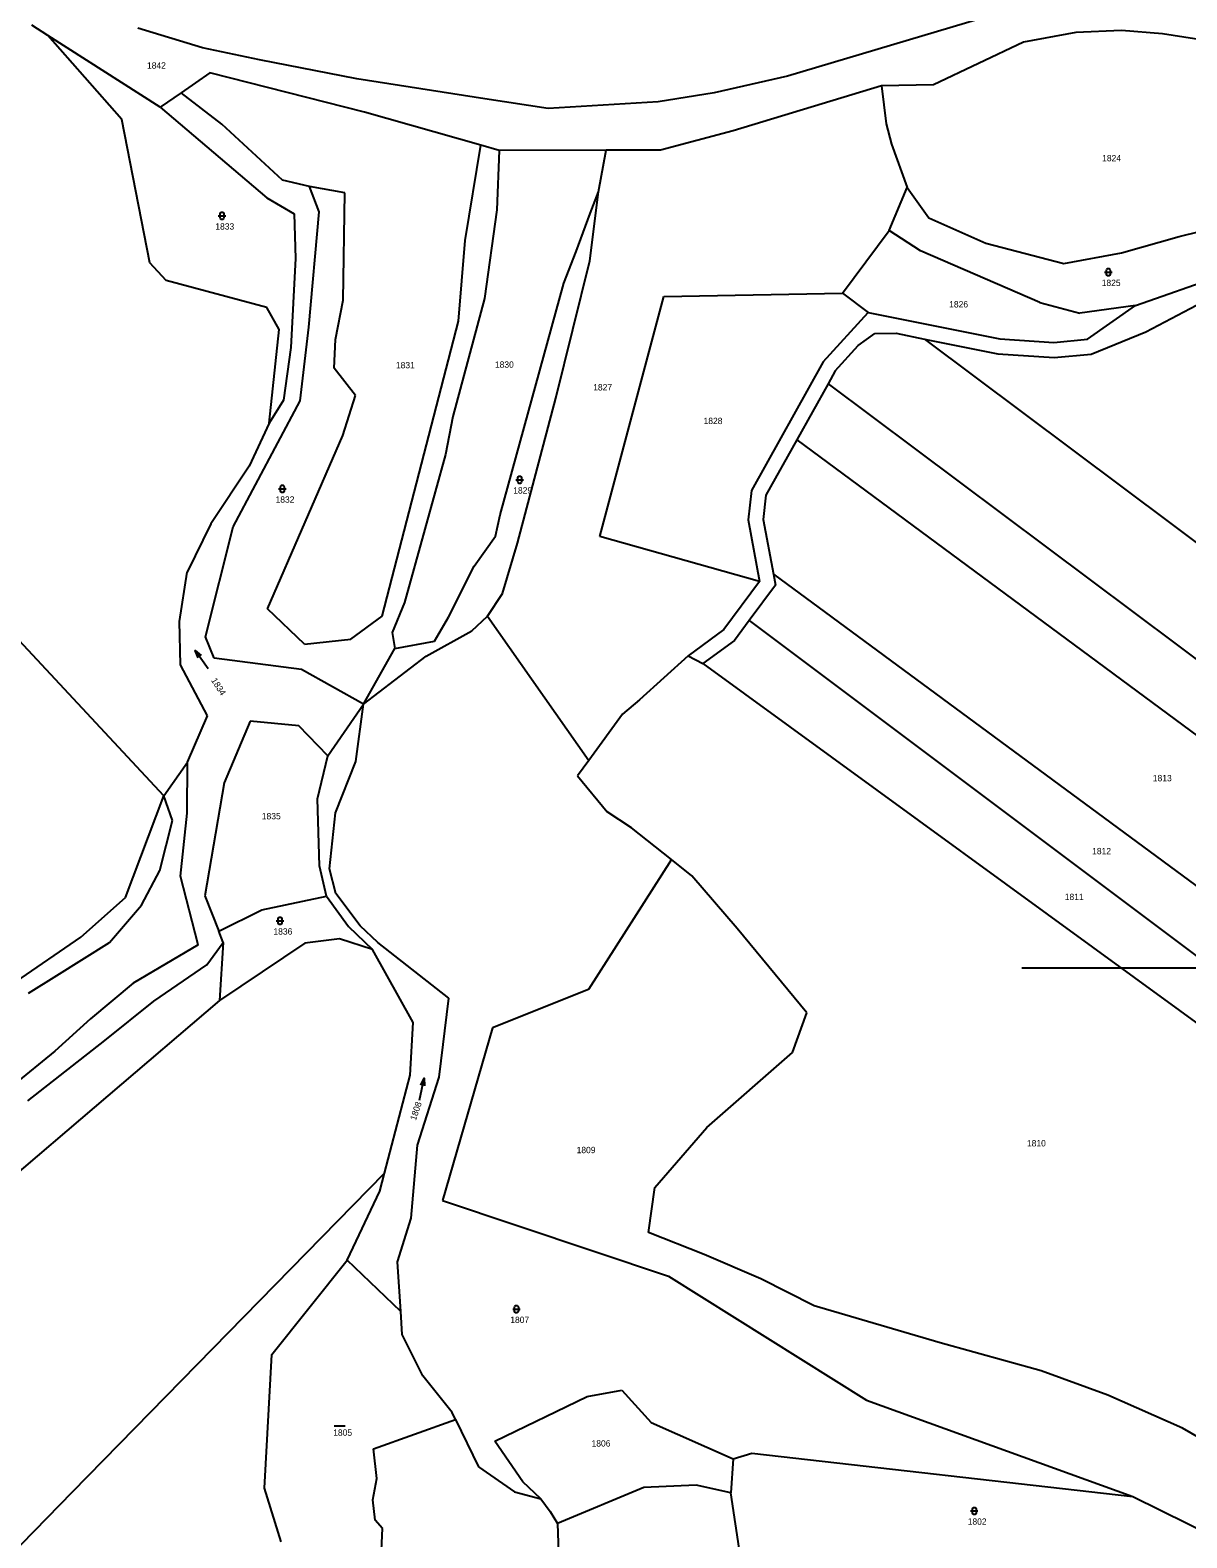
# Model space of a CAD drawing. Extents: x -802857 to -799647, y -1020285 to -1015884.
# Drawn here: x -802140.5 to -801830.8, y -1017652.7 to -1017248.9 of the extents above; entities that cross this region are included whole.
import ezdxf

# ---------------------------------------------------------------- set-up
doc = ezdxf.new("R2010")
doc.units = 0
for name, color, linetype in [('Default', 7, 'Continuous'), ('KLADY_ZMVM', 7, 'Continuous'), ('KN_HRANICE', 7, 'Continuous'), ('KN_KULTURY', 7, 'Continuous'), ('KN_PARCELY', 7, 'Continuous')]:
    doc.layers.add(name, color=color, linetype=linetype)

# ---------------------------------------------------------------- blocks, each defined once
blk = doc.blocks.new('316')
at = {"layer": 'Default'}
for points in [[(-1, 1), (0.27, 1), (1, 1)], [(-0.5, 1.5), (-0.4, 1.79), (-0.15, 1.97), (0.16, 1.97), (0.41, 1.79), (0.51, 1.5), (0.51, 0.5), (0.41, 0.21), (0.16, 0.03), (-0.15, 0.03), (-0.4, 0.21), (-0.5, 0.5), (-0.5, 1.5)]]:
    blk.add_lwpolyline(points, dxfattribs=at)
blk = doc.blocks.new('802')
at = {"layer": 'Default'}
blk.add_line((-3, 0), (3, 0), dxfattribs=at)
blk.add_lwpolyline([(1, 0.5), (3, 0), (1, -0.5)], dxfattribs=at)
blk = doc.blocks.new('804')
at = {"layer": 'Default'}
blk.add_line((-1.5, 0), (1.5, 0), dxfattribs=at)

msp = doc.modelspace()

# ---------------------------------------------------------------- linework, layer by layer
at = {"layer": 'KLADY_ZMVM'}
msp.add_lwpolyline([(-801875, -1017500), (-801250, -1017500), (-801043.11, -1017500)], dxfattribs=at)
at = {"layer": 'KN_HRANICE'}
for p, q in [((-802135.82, -1017250.34), (-802140.07, -1017247.63)), ((-802094.38, -1017253.69), (-802111.69, -1017248.4)), ((-801885.86, -1017245.79), (-801937.77, -1017261.22)), ((-802115.97, -1017272.85), (-802135.82, -1017250.34)), ((-802105.66, -1017269.56), (-802135.82, -1017250.34)), ((-801874.58, -1017252.18), (-801898.61, -1017263.57)), ((-801860.52, -1017249.56), (-801874.58, -1017252.18)), ((-801848.33, -1017249.03), (-801860.52, -1017249.56)), ((-801837.36, -1017249.87), (-801848.33, -1017249.03)), ((-801825.91, -1017251.69), (-801837.36, -1017249.87)), ((-802079.15, -1017256.83), (-802094.38, -1017253.69)), ((-802092.36, -1017260.39), (-802100.06, -1017265.7)), ((-802050.96, -1017270.85), (-802092.36, -1017260.39)), ((-802053.05, -1017261.93), (-802079.15, -1017256.83)), ((-802018.77, -1017267.32), (-802053.05, -1017261.93)), ((-801937.77, -1017261.22), (-801957.35, -1017265.73)), ((-801912.59, -1017263.88), (-801952.27, -1017275.87)), ((-801898.61, -1017263.57), (-801912.59, -1017263.88)), ((-801912.59, -1017263.88), (-801911.34, -1017274.02)), ((-802100.06, -1017265.7), (-802105.66, -1017269.56)), ((-802089.22, -1017274.06), (-802100.06, -1017265.7)), ((-802001.86, -1017269.94), (-802018.77, -1017267.32)), ((-801972.34, -1017268.15), (-802001.86, -1017269.94)), ((-801957.35, -1017265.73), (-801972.34, -1017268.15)), ((-802105.66, -1017269.56), (-802077.17, -1017293.84)), ((-802019.81, -1017279.73), (-802050.96, -1017270.85)), ((-802108.43, -1017311.28), (-802115.97, -1017272.85)), ((-802072.93, -1017289.09), (-802089.22, -1017274.06)), ((-801952.27, -1017275.87), (-801971.78, -1017281.07)), ((-801911.34, -1017274.02), (-801909.91, -1017279.49)), ((-802024.05, -1017305.27), (-802019.81, -1017279.73)), ((-802014.98, -1017281.11), (-802019.81, -1017279.73)), ((-801909.91, -1017279.49), (-801905.73, -1017291.03)), ((-802014.98, -1017281.11), (-802015.53, -1017297.03)), ((-801986.28, -1017281.08), (-802014.98, -1017281.11)), ((-801988.37, -1017292.2), (-801986.28, -1017281.08)), ((-801971.78, -1017281.07), (-801986.28, -1017281.08)), ((-802065.76, -1017290.83), (-802072.93, -1017289.09)), ((-802063.17, -1017297.59), (-802065.76, -1017290.83)), ((-802056.25, -1017292.52), (-802065.76, -1017290.83)), ((-802056.66, -1017321.24), (-802056.25, -1017292.52)), ((-801990.7, -1017310.73), (-801988.37, -1017292.2)), ((-801990.6, -1017297.99), (-801988.37, -1017292.2)), ((-801910.52, -1017302.62), (-801905.73, -1017291.03)), ((-801905.73, -1017291.03), (-801899.92, -1017299.2)), ((-802077.17, -1017293.84), (-802069.8, -1017298.14)), ((-802015.53, -1017297.03), (-802018.85, -1017320.82)), ((-802069.8, -1017298.14), (-802069.48, -1017310.1)), ((-802065.91, -1017328.48), (-802063.17, -1017297.59)), ((-801994.28, -1017308.23), (-801990.6, -1017297.99)), ((-801899.92, -1017299.2), (-801884.62, -1017305.93)), ((-801832.86, -1017304.19), (-801816.89, -1017300.2)), ((-801922.99, -1017319.4), (-801910.52, -1017302.62)), ((-801902.09, -1017308), (-801910.52, -1017302.62)), ((-801848.32, -1017308.55), (-801832.86, -1017304.19)), ((-802025.84, -1017326.85), (-802024.05, -1017305.27)), ((-801997.65, -1017316.67), (-801994.28, -1017308.23)), ((-801870.21, -1017321.88), (-801902.09, -1017308)), ((-801884.62, -1017305.93), (-801863.71, -1017311.42)), ((-801863.71, -1017311.42), (-801848.32, -1017308.55)), ((-802104.1, -1017315.93), (-802108.43, -1017311.28)), ((-802069.48, -1017310.1), (-802070.75, -1017333.91)), ((-801999.74, -1017347.44), (-801990.7, -1017310.73)), ((-802104.72, -1017453.99), (-802234.28, -1017315.12)), ((-802077.12, -1017323.21), (-802104.1, -1017315.93)), ((-802014.71, -1017378.73), (-801997.65, -1017316.67)), ((-801844.56, -1017322.69), (-801821.66, -1017314.59)), ((-802058.72, -1017331.81), (-802056.66, -1017321.24)), ((-802018.85, -1017320.82), (-802027.34, -1017352.4)), ((-801987.95, -1017384.56), (-801970.88, -1017320.22)), ((-801970.88, -1017320.22), (-801922.99, -1017319.4)), ((-801922.99, -1017319.4), (-801916.15, -1017324.52)), ((-801841.82, -1017329.72), (-801824.8, -1017320.76)), ((-802073.83, -1017329.13), (-802077.12, -1017323.21)), ((-801928.21, -1017337.78), (-801916.15, -1017324.52)), ((-801916.15, -1017324.52), (-801880.89, -1017331.62)), ((-801870.21, -1017321.88), (-801859.44, -1017324.75)), ((-801844.56, -1017322.69), (-801859.44, -1017324.75)), ((-801857.38, -1017331.72), (-801844.56, -1017322.69)), ((-802076.48, -1017354.13), (-802073.83, -1017329.13)), ((-802068.2, -1017348.18), (-802065.91, -1017328.48)), ((-802046.3, -1017405.83), (-802025.84, -1017326.85)), ((-802059.12, -1017339.45), (-802058.72, -1017331.81)), ((-801924.94, -1017340.13), (-801918.78, -1017333.36)), ((-801918.78, -1017333.36), (-801914.38, -1017330.18)), ((-801914.38, -1017330.18), (-801908.67, -1017330.11)), ((-801908.67, -1017330.11), (-801901.1, -1017331.64)), ((-801901.1, -1017331.64), (-801881.43, -1017335.59)), ((-801901.1, -1017331.64), (-801752.52, -1017442.84)), ((-801880.89, -1017331.62), (-801866.4, -1017332.56)), ((-801866.4, -1017332.56), (-801857.38, -1017331.72)), ((-801856.42, -1017335.65), (-801841.82, -1017329.72)), ((-802070.75, -1017333.91), (-802072.65, -1017348.05)), ((-801881.43, -1017335.59), (-801866.34, -1017336.57)), ((-801866.34, -1017336.57), (-801856.42, -1017335.65)), ((-802053.38, -1017346.72), (-802059.12, -1017339.45)), ((-801928.21, -1017337.78), (-801947.39, -1017372.21)), ((-801924.94, -1017340.13), (-801926.87, -1017343.6)), ((-801926.87, -1017343.6), (-801935.26, -1017358.65)), ((-801926.87, -1017343.6), (-801768.75, -1017461.94)), ((-802086.2, -1017381.95), (-802068.2, -1017348.18)), ((-802072.65, -1017348.05), (-802076.48, -1017354.13)), ((-802056.78, -1017357.44), (-802053.38, -1017346.72)), ((-802010.06, -1017386.33), (-801999.74, -1017347.44)), ((-802027.34, -1017352.4), (-802029.33, -1017362.55)), ((-802076.48, -1017354.13), (-802081.89, -1017365.72)), ((-802076.93, -1017403.91), (-802056.78, -1017357.44)), ((-801935.26, -1017358.65), (-801943.51, -1017373.46)), ((-801935.26, -1017358.65), (-801779.08, -1017474.09)), ((-802029.33, -1017362.55), (-802034.83, -1017382.57)), ((-802081.89, -1017365.72), (-802092.18, -1017381.13)), ((-801947.39, -1017372.21), (-801948.3, -1017380.1)), ((-801943.51, -1017373.46), (-801944.26, -1017379.96)), ((-802092.18, -1017381.13), (-802098.46, -1017394.03)), ((-802015.89, -1017384.46), (-802014.71, -1017378.73)), ((-801948.3, -1017380.1), (-801945.23, -1017396.56)), ((-801944.26, -1017379.96), (-801941.53, -1017394.58)), ((-802093.54, -1017411.38), (-802086.2, -1017381.95)), ((-802034.83, -1017382.57), (-802040.31, -1017402.18)), ((-802021.65, -1017392.45), (-802015.89, -1017384.46)), ((-801945.23, -1017396.56), (-801987.95, -1017384.56)), ((-802014.08, -1017399.77), (-802010.06, -1017386.33)), ((-802028.5, -1017406.11), (-802021.65, -1017392.45)), ((-802100.54, -1017407.26), (-802098.46, -1017394.03)), ((-801945.23, -1017396.56), (-801954.81, -1017409.47)), ((-801940.98, -1017397.54), (-801947.99, -1017406.99)), ((-801941.53, -1017394.58), (-801940.98, -1017397.54)), ((-801941.53, -1017394.58), (-801799.52, -1017499.3)), ((-802018.05, -1017405.89), (-802014.08, -1017399.77)), ((-802067.06, -1017413.33), (-802076.93, -1017403.91)), ((-802054.67, -1017411.98), (-802046.3, -1017405.83)), ((-802040.31, -1017402.18), (-802043.62, -1017410.23)), ((-802022.25, -1017409.81), (-802018.05, -1017405.89)), ((-802018.05, -1017405.89), (-801990.91, -1017444.47)), ((-802100.23, -1017418.86), (-802100.54, -1017407.26)), ((-802034.52, -1017416.58), (-802022.25, -1017409.81)), ((-802032.22, -1017412.54), (-802028.5, -1017406.11)), ((-801954.81, -1017409.47), (-801964.29, -1017416.44)), ((-801947.99, -1017406.99), (-801951.96, -1017412.34)), ((-801947.99, -1017406.99), (-801809.18, -1017511.2)), ((-802091.22, -1017417.12), (-802093.54, -1017411.38)), ((-802067.06, -1017413.33), (-802054.67, -1017411.98)), ((-802043.62, -1017410.23), (-802042.85, -1017414.5)), ((-802042.85, -1017414.5), (-802032.22, -1017412.54)), ((-801951.96, -1017412.34), (-801960.43, -1017418.57)), ((-802067.89, -1017420.13), (-802091.22, -1017417.12)), ((-802051.27, -1017429.42), (-802042.85, -1017414.5)), ((-802051.27, -1017429.42), (-802034.52, -1017416.58)), ((-801964.29, -1017416.44), (-801977.33, -1017428.3)), ((-801964.29, -1017416.44), (-801960.43, -1017418.57)), ((-802093.06, -1017432.53), (-802100.23, -1017418.86)), ((-802051.27, -1017429.42), (-802067.89, -1017420.13)), ((-801960.43, -1017418.57), (-801819.24, -1017521.36)), ((-802060.85, -1017443.3), (-802051.27, -1017429.42)), ((-802053.3, -1017444.75), (-802051.27, -1017429.42)), ((-801977.33, -1017428.3), (-801981.94, -1017432.13)), ((-802098.34, -1017444.92), (-802093.06, -1017432.53)), ((-802081.64, -1017433.99), (-802088.57, -1017450.52)), ((-802068.53, -1017435.23), (-802081.64, -1017433.99)), ((-801981.94, -1017432.13), (-801990.91, -1017444.47)), ((-802060.85, -1017443.3), (-802068.53, -1017435.23)), ((-802104.72, -1017453.99), (-802098.34, -1017444.92)), ((-802098.44, -1017458.57), (-802098.34, -1017444.92)), ((-802063.57, -1017454.79), (-802060.85, -1017443.3)), ((-802058.8, -1017458.48), (-802053.3, -1017444.75)), ((-801990.91, -1017444.47), (-801993.92, -1017448.6)), ((-801993.92, -1017448.6), (-801986, -1017458.26)), ((-802115.01, -1017481.22), (-802104.72, -1017453.99)), ((-802102.44, -1017460.62), (-802104.72, -1017453.99)), ((-802088.57, -1017450.52), (-802093.7, -1017480.76)), ((-802063.08, -1017472.7), (-802063.57, -1017454.79)), ((-802060.32, -1017473.5), (-802058.8, -1017458.48)), ((-801979.48, -1017462.54), (-801986, -1017458.26)), ((-802105.82, -1017473.99), (-802102.44, -1017460.62)), ((-802100.3, -1017475.48), (-802098.44, -1017458.57)), ((-801968.81, -1017471.06), (-801979.48, -1017462.54)), ((-802110.74, -1017483.29), (-802105.82, -1017473.99)), ((-802061.2, -1017480.82), (-802063.08, -1017472.7)), ((-802058.68, -1017480.13), (-802060.32, -1017473.5)), ((-801968.81, -1017471.06), (-801991.01, -1017505.82)), ((-801963.34, -1017475.43), (-801968.81, -1017471.06)), ((-802095.56, -1017493.88), (-802100.3, -1017475.48)), ((-801951.18, -1017489.47), (-801963.34, -1017475.43)), ((-802126.91, -1017491.79), (-802115.01, -1017481.22)), ((-802093.7, -1017480.76), (-802089.98, -1017490.25)), ((-802078.47, -1017484.51), (-802061.2, -1017480.82)), ((-802061.2, -1017480.82), (-802055.25, -1017488.94)), ((-802052.12, -1017488.76), (-802058.68, -1017480.13)), ((-802119.31, -1017493.23), (-802110.74, -1017483.29)), ((-802089.98, -1017490.25), (-802078.47, -1017484.51)), ((-802088.79, -1017493.29), (-802089.98, -1017490.25)), ((-802055.25, -1017488.94), (-802048.87, -1017495.15)), ((-802047.43, -1017493.24), (-802052.12, -1017488.76)), ((-801932.6, -1017512.07), (-801951.18, -1017489.47)), ((-802144.39, -1017503.8), (-802126.91, -1017491.79)), ((-802133.41, -1017502.05), (-802119.31, -1017493.23)), ((-802095.56, -1017493.88), (-802112.95, -1017504.15)), ((-802093.25, -1017499.27), (-802088.79, -1017493.29)), ((-802088.79, -1017493.29), (-802089.8, -1017508.76)), ((-802066.93, -1017493.44), (-802089.8, -1017508.76)), ((-802057.71, -1017492.3), (-802066.93, -1017493.44)), ((-802048.87, -1017495.15), (-802057.71, -1017492.3)), ((-802028.39, -1017508.13), (-802047.43, -1017493.24)), ((-802037.98, -1017514.66), (-802048.87, -1017495.15)), ((-802140.95, -1017506.78), (-802133.41, -1017502.05)), ((-802107.41, -1017508.95), (-802093.25, -1017499.27)), ((-802112.95, -1017504.15), (-802124.38, -1017513.72)), ((-801991.01, -1017505.82), (-802016.71, -1017516.13)), ((-802089.8, -1017508.76), (-802158.4, -1017567.31)), ((-802120.51, -1017519.45), (-802107.41, -1017508.95)), ((-802031.03, -1017529.3), (-802028.39, -1017508.13)), ((-802124.38, -1017513.72), (-802133.87, -1017522.32)), ((-802038.74, -1017528.77), (-802037.98, -1017514.66)), ((-801936.43, -1017522.68), (-801932.6, -1017512.07)), ((-802016.71, -1017516.13), (-802030.12, -1017562.37)), ((-802133.87, -1017522.32), (-802145.05, -1017531.44)), ((-802141.11, -1017535.62), (-802120.51, -1017519.45)), ((-801959.3, -1017542.75), (-801936.43, -1017522.68)), ((-802045.6, -1017555.03), (-802038.74, -1017528.77)), ((-802036.81, -1017547.5), (-802031.03, -1017529.3)), ((-801973.25, -1017558.82), (-801959.3, -1017542.75)), ((-802038.48, -1017567.05), (-802036.81, -1017547.5)), ((-802129.14, -1017640.4), (-802045.6, -1017555.03)), ((-802046.85, -1017559.81), (-802045.6, -1017555.03)), ((-801974.92, -1017570.9), (-801973.25, -1017558.82)), ((-802055.66, -1017578.31), (-802046.85, -1017559.81)), ((-802030.12, -1017562.37), (-801969.63, -1017582.61)), ((-802042.13, -1017578.79), (-802038.48, -1017567.05)), ((-801960.08, -1017576.81), (-801974.92, -1017570.9)), ((-802075.83, -1017603.58), (-802055.66, -1017578.31)), ((-802041.24, -1017592.08), (-802055.66, -1017578.31)), ((-802041.24, -1017592.08), (-802042.13, -1017578.79)), ((-801944.86, -1017583.35), (-801960.08, -1017576.81)), ((-801969.63, -1017582.61), (-801916.56, -1017615.84)), ((-801930.62, -1017590.56), (-801944.86, -1017583.35)), ((-801896.85, -1017600.49), (-801930.62, -1017590.56)), ((-802040.91, -1017598.18), (-802041.24, -1017592.08)), ((-802035.33, -1017609.27), (-802040.91, -1017598.18)), ((-802077.76, -1017639.34), (-802075.83, -1017603.58)), ((-801869.8, -1017607.95), (-801896.85, -1017600.49)), ((-801852, -1017614.46), (-801869.8, -1017607.95)), ((-802027.48, -1017619.13), (-802035.33, -1017609.27)), ((-802016.11, -1017626.77), (-801991.36, -1017614.81)), ((-801991.36, -1017614.81), (-801982.05, -1017613.11)), ((-801982.05, -1017613.11), (-801974.22, -1017621.75)), ((-801916.56, -1017615.84), (-801845.29, -1017641.57)), ((-801832.01, -1017623.28), (-801852, -1017614.46)), ((-802026.6, -1017620.95), (-802027.48, -1017619.13)), ((-802048.6, -1017628.82), (-802026.6, -1017620.95)), ((-802026.6, -1017620.95), (-802020.45, -1017633.65)), ((-801974.22, -1017621.75), (-801952.31, -1017631.49)), ((-801804.69, -1017639.18), (-801832.01, -1017623.28)), ((-802008.63, -1017637.65), (-802016.11, -1017626.77)), ((-802047.68, -1017636.82), (-802048.6, -1017628.82)), ((-801952.31, -1017631.49), (-801952.94, -1017640.64)), ((-801952.31, -1017631.49), (-801947.31, -1017630)), ((-801947.31, -1017630), (-801845.29, -1017641.57)), ((-802020.45, -1017633.65), (-802010.81, -1017640.36)), ((-802073.29, -1017653.73), (-802077.76, -1017639.34)), ((-802048.77, -1017642.46), (-802047.68, -1017636.82)), ((-802003.75, -1017642.22), (-802008.63, -1017637.65)), ((-801976.22, -1017639.19), (-801999.28, -1017648.83)), ((-801962.21, -1017638.54), (-801976.22, -1017639.19)), ((-801952.94, -1017640.64), (-801962.21, -1017638.54)), ((-802214.72, -1017727.85), (-802129.14, -1017640.4)), ((-802048.15, -1017647.93), (-802048.77, -1017642.46)), ((-802010.81, -1017640.36), (-802003.75, -1017642.22)), ((-802003.75, -1017642.22), (-802001.28, -1017645.63)), ((-801950.38, -1017657.2), (-801952.94, -1017640.64)), ((-801845.29, -1017641.57), (-801823.05, -1017652.62)), ((-802046.13, -1017650.15), (-802048.15, -1017647.93)), ((-802001.28, -1017645.63), (-801999.28, -1017648.83)), ((-802046.96, -1017667.05), (-802046.13, -1017650.15)), ((-801999.28, -1017648.83), (-801998.77, -1017663.53))]:
    msp.add_line(p, q, dxfattribs=at)

# ---------------------------------------------------------------- block references
at = {"layer": 'KN_KULTURY'}
for name, p in [('316', (-802089.13, -1017299.63)), ('316', (-801851.84, -1017314.75)), ('316', (-802009.45, -1017370.32)), ('316', (-802073.01, -1017372.77)), ('316', (-802073.63, -1017488.44)), ('316', (-802010.31, -1017592.45)), ('804', (-802057.65, -1017622.65)), ('316', (-801887.74, -1017646.48))]:
    msp.add_blockref(name, p, dxfattribs=at)
for p, rotation in [((-802094.57, -1017417.5), 125.42046100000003), ((-802035.62, -1017532.53), 78.20873900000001)]:
    msp.add_blockref('802', p, dxfattribs=dict(at, rotation=rotation))

# ---------------------------------------------------------------- texts
at = {"layer": 'KN_PARCELY'}
for s, p in [('1842', (-802109.23, -1017259.23)), ('1824', (-801853.49, -1017284.04)), ('1833', (-802090.94, -1017302.33)), ('1825', (-801853.61, -1017317.45)), ('1826', (-801894.45, -1017323.19)), ('1831', (-802042.58, -1017339.48)), ('1830', (-802016.07, -1017339.33)), ('1827', (-801989.76, -1017345.42)), ('1828', (-801960.21, -1017354.42)), ('1832', (-802074.81, -1017375.47)), ('1829', (-802011.17, -1017373.02)), ('1813', (-801839.92, -1017450.07)), ('1835', (-802078.48, -1017460.27)), ('1812', (-801856.17, -1017469.62)), ('1811', (-801863.5, -1017481.88)), ('1836', (-802075.37, -1017491.14)), ('1810', (-801873.63, -1017547.86)), ('1809', (-801994.2, -1017549.67)), ('1807', (-802011.96, -1017595.15)), ('1805', (-802059.37, -1017625.35)), ('1806', (-801990.2, -1017628.23)), ('1802', (-801889.49, -1017649.18))]:
    msp.add_text(s, height=1.7, dxfattribs=at).set_placement(p)
for s, rotation, p in [('1834', 302.579, (-802092.12, -1017423.05)), ('1808', 71.562, (-802037.24, -1017541.04))]:
    msp.add_text(s, height=1.7, rotation=rotation, dxfattribs=at).set_placement(p)

doc.saveas('drawing.dxf')
